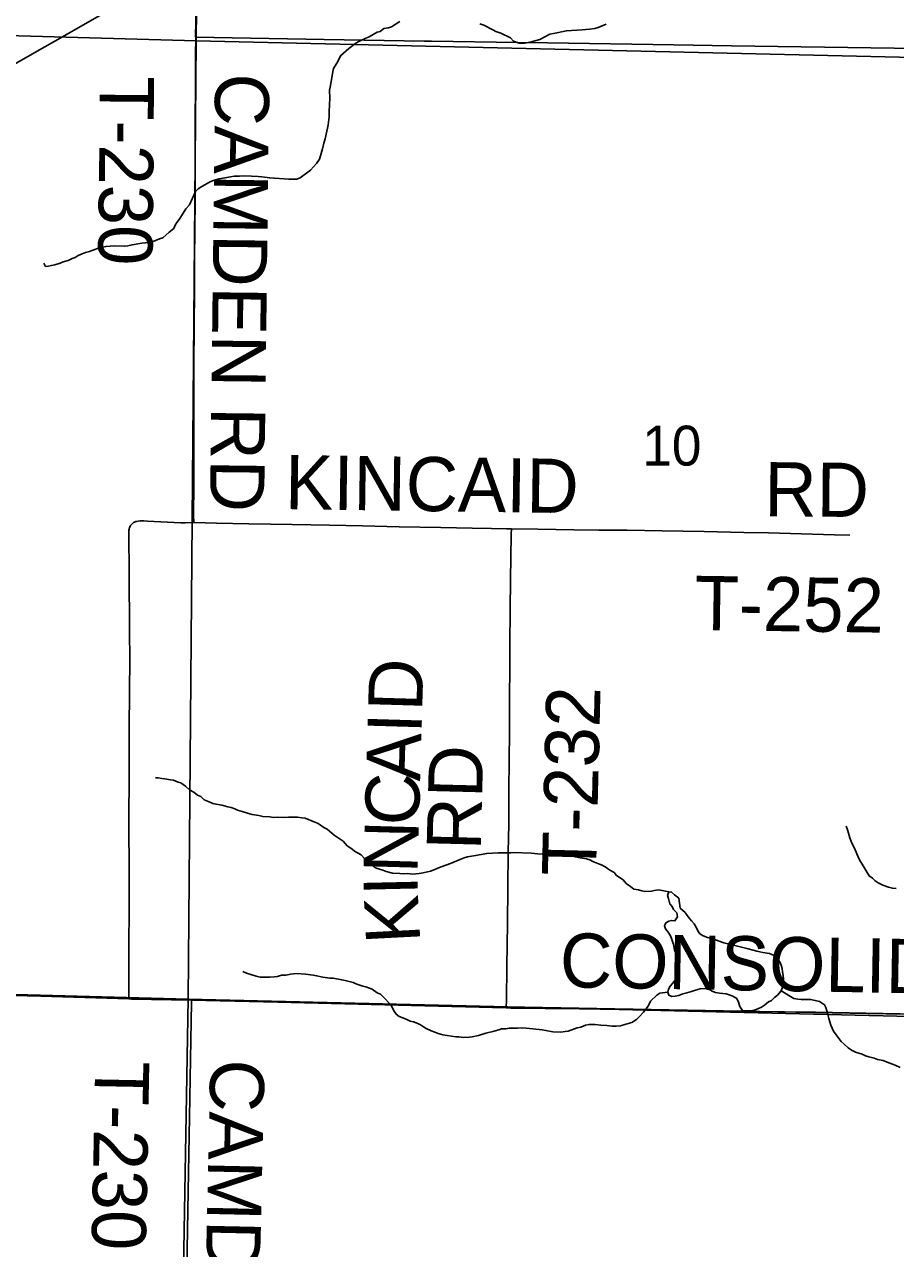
# Model space of a CAD drawing. Extents: x 0 to 34, y 0 to 22.
# Drawn here: x 25.481 to 25.938, y 17.215 to 17.857 of the extents above; entities that cross this region are included whole.
import ezdxf

# ---------------------------------------------------------------- set-up
doc = ezdxf.new("R2010")
doc.units = 0
for name, color, linetype in [('GM_X_Corporation', 7, 'Continuous'), ('GM_X_County_Road', 7, 'Continuous'), ('GM_X_County_Road_Text', 7, 'Continuous'), ('GM_X_Minor_River', 7, 'Continuous'), ('GM_X_Section', 7, 'Continuous'), ('GM_X_Section_Text', 7, 'Continuous'), ('GM_X_State_Route', 7, 'Continuous'), ('GM_X_Township', 7, 'Continuous'), ('GM_X_Township_Road', 7, 'Continuous'), ('GM_X_Township_Road_Text', 7, 'Continuous'), ('SC_Scratch1', 7, 'Continuous')]:
    doc.layers.add(name, color=color, linetype=linetype)

msp = doc.modelspace()

# ---------------------------------------------------------------- linework, layer by layer
at = {"layer": 'GM_X_Corporation'}
msp.add_lwpolyline([(26.05911, 17.84256), (25.85184, 17.84569), (25.82157, 17.84614), (25.75513, 17.84714), (25.73967, 17.84737), (25.69432, 17.84806), (25.69042, 17.84812), (25.63797, 17.84891), (25.57052, 17.85015), (25.57131, 17.89123)], dxfattribs=at)
at = {"layer": 'GM_X_County_Road'}
for points in [[(25.01331, 17.35912), (25.07885, 17.35735), (25.11483, 17.35638), (25.16488, 17.35487), (25.21328, 17.3539), (25.30505, 17.35181), (25.37943, 17.34967), (25.44651, 17.34801), (25.48937, 17.34696), (25.53551, 17.34557)], [(25.53551, 17.34557), (25.53688, 17.34553), (25.56843, 17.34486)], [(25.56843, 17.34486), (25.6136, 17.34389), (25.65584, 17.34285), (25.69091, 17.34191), (25.73359, 17.34085), (25.73594, 17.34079), (25.77197, 17.34038), (25.7937, 17.33996), (25.81638, 17.33963), (25.86328, 17.33902), (25.89585, 17.33857), (25.94025, 17.33778), (25.97348, 17.3371), (26.02504, 17.33614), (26.09925, 17.33463), (26.12596, 17.33417), (26.16259, 17.33362), (26.17764, 17.33314)]]:
    msp.add_lwpolyline(points, dxfattribs=at)
at = {"layer": 'GM_X_Minor_River'}
for points in [[(25.67769, 17.85832), (25.67341, 17.85562), (25.67168, 17.85511), (25.66938, 17.85462), (25.66743, 17.85316), (25.6659, 17.85284), (25.66163, 17.85033), (25.65989, 17.84963), (25.6566, 17.84803), (25.65466, 17.84696), (25.65095, 17.84424), (25.64664, 17.8404), (25.6452, 17.83741), (25.64298, 17.83369), (25.64254, 17.83219), (25.64227, 17.82992), (25.64111, 17.82388), (25.64087, 17.82237), (25.64091, 17.81819), (25.64066, 17.81117), (25.64056, 17.80832), (25.64004, 17.80416), (25.63979, 17.80246), (25.63935, 17.80076), (25.63845, 17.79681), (25.6378, 17.79455), (25.63712, 17.79153), (25.63646, 17.78908), (25.6356, 17.78608), (25.634, 17.78385), (25.63083, 17.78035), (25.62537, 17.77636), (25.62363, 17.77567), (25.61945, 17.77562)], [(25.78601, 17.85701), (25.78177, 17.85526), (25.78004, 17.85475), (25.77736, 17.85427), (25.77526, 17.85416), (25.77336, 17.85403), (25.76783, 17.85366), (25.76517, 17.85356), (25.75827, 17.85209), (25.75636, 17.85178), (25.75112, 17.84892), (25.7492, 17.84842), (25.74613, 17.84757), (25.74307, 17.84692), (25.74041, 17.84701), (25.7374, 17.84807), (25.73576, 17.84984), (25.73071, 17.85229), (25.72808, 17.85314), (25.72659, 17.85395), (25.72173, 17.8564), (25.71967, 17.85723)], [(25.61945, 17.77562), (25.61699, 17.7759), (25.61187, 17.77626), (25.6094, 17.77635), (25.60523, 17.77688), (25.60334, 17.77713), (25.59631, 17.77738), (25.59365, 17.77728), (25.59079, 17.77719), (25.58888, 17.77687), (25.58295, 17.77575), (25.57969, 17.77492), (25.57776, 17.77403), (25.57388, 17.77189), (25.57193, 17.77063), (25.57055, 17.76916), (25.56726, 17.76224), (25.56547, 17.76002), (25.56406, 17.75779), (25.56186, 17.75445), (25.56066, 17.75297), (25.55985, 17.75148), (25.55903, 17.7498), (25.55668, 17.74779), (25.55334, 17.74487), (25.55161, 17.74436), (25.54833, 17.74295), (25.54681, 17.74282), (25.54432, 17.74233), (25.5424, 17.74202), (25.53724, 17.74125), (25.53495, 17.74076), (25.53322, 17.74044), (25.52772, 17.74063), (25.52353, 17.7404), (25.52161, 17.7399), (25.5195, 17.7394), (25.51661, 17.73836), (25.51487, 17.73766), (25.51276, 17.73716), (25.51103, 17.73646), (25.50891, 17.73559), (25.50735, 17.7345), (25.50581, 17.73399), (25.50368, 17.73292), (25.50099, 17.73225), (25.49945, 17.73155), (25.49657, 17.7307), (25.49484, 17.73038), (25.49331, 17.73005), (25.49178, 17.72992), (25.4909, 17.73166)], [(25.55286, 17.46125), (25.55097, 17.46151), (25.54945, 17.46156)], [(25.81885, 17.40184), (25.81356, 17.40278), (25.81126, 17.40248), (25.80973, 17.40216), (25.8063, 17.4019), (25.80479, 17.40233), (25.80291, 17.40277), (25.80045, 17.40324), (25.79879, 17.40463), (25.79657, 17.40622), (25.79492, 17.40799), (25.79139, 17.41039), (25.79011, 17.41196), (25.78787, 17.41318), (25.78602, 17.41457), (25.78397, 17.41578), (25.78247, 17.41621), (25.77891, 17.41767), (25.77741, 17.41848), (25.77572, 17.41911), (25.77232, 17.41961), (25.76987, 17.42007), (25.76798, 17.42052), (25.764, 17.42085), (25.7604, 17.42116), (25.75888, 17.42122), (25.75509, 17.42154), (25.75319, 17.4216), (25.75015, 17.42171), (25.74655, 17.42202), (25.73743, 17.42234), (25.73591, 17.4222), (25.73306, 17.4223), (25.72925, 17.42225), (25.72335, 17.42188), (25.71742, 17.42076), (25.71321, 17.42015), (25.71148, 17.41964), (25.70878, 17.41859), (25.70434, 17.41665), (25.69934, 17.41493), (25.6976, 17.41423), (25.69606, 17.41352), (25.69374, 17.41265), (25.68991, 17.41165), (25.6878, 17.41134), (25.68437, 17.41108), (25.68191, 17.41136), (25.67981, 17.41124), (25.67773, 17.41131), (25.67394, 17.41163), (25.67054, 17.41251), (25.66885, 17.41314), (25.66528, 17.41421), (25.6625, 17.41621), (25.65918, 17.41918), (25.65735, 17.42114), (25.654, 17.42316), (25.65252, 17.42435), (25.6501, 17.42595), (25.6479, 17.42831), (25.64326, 17.43151), (25.63957, 17.43468), (25.63789, 17.4355), (25.63493, 17.43769), (25.63305, 17.43833), (25.62799, 17.4404), (25.62628, 17.44065), (25.62401, 17.44092), (25.62135, 17.44101), (25.61926, 17.44089), (25.6164, 17.4408), (25.61355, 17.4409), (25.61127, 17.44079), (25.60957, 17.44104), (25.60578, 17.44136), (25.6037, 17.44182), (25.6003, 17.44231), (25.59785, 17.44297), (25.59503, 17.44383), (25.59258, 17.44467), (25.59108, 17.4453), (25.58921, 17.44593), (25.58751, 17.44637), (25.58431, 17.44724), (25.58128, 17.44773), (25.57959, 17.44817), (25.57772, 17.44899), (25.57509, 17.45003), (25.57325, 17.45181), (25.57156, 17.45243), (25.56953, 17.45402), (25.56729, 17.45524), (25.56527, 17.45721), (25.56286, 17.45901), (25.56135, 17.45925), (25.55891, 17.46028), (25.5574, 17.46053), (25.55437, 17.46101), (25.55286, 17.46125)], [(25.93812, 17.40357), (25.93622, 17.40364), (25.93415, 17.40428), (25.93114, 17.40534), (25.92871, 17.40656), (25.92723, 17.40756), (25.92576, 17.40894), (25.92409, 17.41014), (25.92085, 17.41538), (25.91887, 17.41849), (25.91746, 17.42177), (25.91623, 17.42467), (25.915, 17.42737), (25.91395, 17.43006), (25.91309, 17.43256), (25.91258, 17.43429), (25.91189, 17.43622)], [(25.82405, 17.39843), (25.82183, 17.40022), (25.82036, 17.4016), (25.81885, 17.40184), (25.8182, 17.39977), (25.81872, 17.39823), (25.81938, 17.39555), (25.82066, 17.39399), (25.82137, 17.39244), (25.82302, 17.39067), (25.82351, 17.38857), (25.82211, 17.38653), (25.82041, 17.38677), (25.81887, 17.38645), (25.81732, 17.38555), (25.81669, 17.38386), (25.81721, 17.38233), (25.81848, 17.38057), (25.81974, 17.37863), (25.82043, 17.3767), (25.82112, 17.37459), (25.82162, 17.37248), (25.82194, 17.37095), (25.82371, 17.36709), (25.82422, 17.36555), (25.82433, 17.36327), (25.82444, 17.3608), (25.82381, 17.35911), (25.82297, 17.35705), (25.82215, 17.35537), (25.82076, 17.3537), (25.81957, 17.35223), (25.81876, 17.35073), (25.81832, 17.34904), (25.81883, 17.3475), (25.82052, 17.34687), (25.82224, 17.347), (25.82415, 17.34732), (25.82627, 17.34819), (25.82838, 17.34869), (25.83069, 17.34956), (25.83281, 17.35025), (25.8353, 17.35092), (25.83759, 17.35103), (25.84004, 17.35056), (25.84191, 17.34955), (25.84341, 17.34893), (25.84549, 17.34866), (25.8489, 17.34817), (25.85059, 17.34773), (25.85247, 17.34709), (25.85452, 17.34588), (25.8554, 17.34395), (25.85608, 17.34165), (25.85753, 17.33951), (25.85942, 17.33925), (25.8617, 17.33936), (25.86381, 17.33967), (25.86593, 17.34054), (25.86748, 17.34125), (25.86903, 17.34233), (25.87118, 17.34397), (25.87273, 17.34467), (25.87431, 17.34633), (25.87588, 17.34761), (25.87785, 17.34982), (25.87849, 17.35169), (25.87875, 17.35359), (25.87902, 17.35586), (25.8789, 17.35795), (25.87859, 17.35986), (25.87827, 17.36158), (25.87776, 17.36331), (25.87706, 17.36504), (25.87579, 17.3668), (25.87413, 17.36838), (25.8717, 17.36941), (25.86829, 17.36991), (25.8666, 17.37035), (25.86509, 17.37059), (25.86321, 17.37123), (25.86057, 17.3718)], [(25.86057, 17.3718), (25.85208, 17.37389), (25.85058, 17.37433), (25.84775, 17.37499), (25.84531, 17.37584), (25.84249, 17.37689), (25.84061, 17.37752), (25.8391, 17.37776), (25.83685, 17.3786), (25.83518, 17.3798), (25.8341, 17.38136), (25.83339, 17.3829), (25.83213, 17.38504), (25.83086, 17.3866), (25.82903, 17.38857), (25.8274, 17.3909), (25.82482, 17.39327), (25.82405, 17.39843)], [(25.81832, 17.34904), (25.81412, 17.34862), (25.81256, 17.34753), (25.80922, 17.34442), (25.80799, 17.3418), (25.80559, 17.33865), (25.80323, 17.33627), (25.80185, 17.33479), (25.79951, 17.33317), (25.79586, 17.33215), (25.79355, 17.33147), (25.79127, 17.33136), (25.78917, 17.33124), (25.78634, 17.33172), (25.78311, 17.33184), (25.78027, 17.33212), (25.77704, 17.33224), (25.77512, 17.33173), (25.77261, 17.33068), (25.7707, 17.33037), (25.76607, 17.32863), (25.76455, 17.32849), (25.76226, 17.32819), (25.75808, 17.32834), (25.7543, 17.32904), (25.75241, 17.32929), (25.74748, 17.32985), (25.74218, 17.33041), (25.73952, 17.33031), (25.73514, 17.33028), (25.73342, 17.32996), (25.73113, 17.32985), (25.72959, 17.32933), (25.72652, 17.32849), (25.72288, 17.32766), (25.71904, 17.32647), (25.71559, 17.32564), (25.71406, 17.3255), (25.7112, 17.32541), (25.70874, 17.32568), (25.70703, 17.32574), (25.70022, 17.32674), (25.69778, 17.3274), (25.69609, 17.32822), (25.69421, 17.32885), (25.6916, 17.33008), (25.6901, 17.33089), (25.68862, 17.3319), (25.68712, 17.33271), (25.68487, 17.33354), (25.68318, 17.33398), (25.68131, 17.33481), (25.67924, 17.33564), (25.67737, 17.33628), (25.6757, 17.33767), (25.67444, 17.33961), (25.67338, 17.34193), (25.67027, 17.34545), (25.66751, 17.34802), (25.66583, 17.34884), (25.66323, 17.35064), (25.66173, 17.35126), (25.65985, 17.3519), (25.65835, 17.35233), (25.65515, 17.35339), (25.65328, 17.35422), (25.64895, 17.35532), (25.64724, 17.35556), (25.64271, 17.35648), (25.641, 17.35654), (25.63722, 17.35705), (25.63401, 17.35774), (25.63231, 17.35798), (25.62814, 17.35851), (25.6234, 17.35886), (25.62035, 17.35859), (25.61805, 17.3581), (25.61558, 17.358), (25.61346, 17.35731), (25.61175, 17.35718), (25.60946, 17.35707), (25.60661, 17.35698), (25.60433, 17.35706), (25.60225, 17.35751), (25.59943, 17.35837), (25.59717, 17.35902), (25.59531, 17.36003)], [(25.90131, 17.34102), (25.9006, 17.34256), (25.898, 17.34418), (25.89574, 17.34482), (25.89329, 17.34529), (25.89158, 17.34535), (25.88834, 17.34527), (25.88664, 17.34552), (25.88456, 17.34578), (25.87785, 17.34982)], [(25.94032, 17.30964), (25.9377, 17.31087), (25.93338, 17.31235), (25.93132, 17.31319), (25.9283, 17.31386), (25.92661, 17.31449), (25.92379, 17.31516), (25.9221, 17.31579), (25.92041, 17.31661), (25.91684, 17.31768), (25.91478, 17.3187), (25.91292, 17.31991), (25.9109, 17.32188), (25.90924, 17.32326), (25.9067, 17.32677), (25.90525, 17.32872), (25.90384, 17.33181), (25.90282, 17.33527), (25.90232, 17.33738), (25.90182, 17.33929), (25.90131, 17.34102)]]:
    msp.add_lwpolyline(points, dxfattribs=at)
at = {"layer": 'GM_X_Section'}
for points in [[(25.08458, 18.38093), (25.5617, 18.37181), (25.57628, 18.37165), (25.57077, 17.84822), (25.07407, 17.86217)], [(25.57628, 18.37165), (26.06944, 18.36744), (26.0861, 18.36703), (26.07549, 17.83653), (25.57077, 17.84822)], [(25.57077, 17.84822), (25.56671, 17.3454), (25.06186, 17.35916), (25.07407, 17.86217)], [(25.57077, 17.84822), (26.07549, 17.83653), (26.0699, 17.33338), (25.56671, 17.3454)], [(25.06186, 17.35916), (25.56671, 17.3454), (25.55809, 16.8497), (25.05294, 16.85911)], [(25.56671, 17.3454), (26.0699, 17.33338), (26.0572, 16.84119), (25.55809, 16.8497)]]:
    msp.add_lwpolyline(points, close=True, dxfattribs=at)
at = {"layer": 'GM_X_State_Route'}
msp.add_lwpolyline([(25.11016, 17.62284), (25.11217, 17.62436), (25.11687, 17.62793), (25.13052, 17.63822), (25.13648, 17.64238), (25.13905, 17.6441), (25.14422, 17.64741), (25.15652, 17.65472), (25.19902, 17.67927), (25.23276, 17.69851), (25.25619, 17.71199), (25.28763, 17.7296), (25.31286, 17.74367), (25.39575, 17.79085), (25.42766, 17.8088), (25.431, 17.81069), (25.44905, 17.82093), (25.46468, 17.82988), (25.48739, 17.84275), (25.50061, 17.85033), (25.55054, 17.87902), (25.56703, 17.88848)], dxfattribs=at)
at = {"layer": 'GM_X_Township'}
msp.add_lwpolyline([(24.86059, 17.36313), (25.53318, 17.34594), (25.56701, 17.34529), (25.6976, 17.34237), (25.72151, 17.34163), (25.73372, 17.34145), (26.18926, 17.3331), (26.20844, 17.33277), (26.32558, 17.33128)], dxfattribs=at)
at = {"layer": 'GM_X_Township_Road'}
for points in [[(25.57058, 17.84964), (25.57087, 17.86554), (25.57091, 17.87575), (25.57097, 17.88374), (25.57104, 17.88541), (25.57111, 17.88729), (25.57136, 17.89097)], [(25.56954, 17.59666), (25.5695, 17.59825), (25.56956, 17.61608), (25.56964, 17.65987), (25.5696, 17.67416), (25.56982, 17.70212), (25.56994, 17.7136), (25.57002, 17.73131), (25.5702, 17.7515), (25.57024, 17.76206), (25.57035, 17.77448), (25.57034, 17.78412), (25.5703, 17.79281), (25.57036, 17.80741), (25.57041, 17.82325), (25.57049, 17.84127), (25.57058, 17.84964)], [(25.53551, 17.34557), (25.53551, 17.34739), (25.53557, 17.36654), (25.53572, 17.39948), (25.53567, 17.41564), (25.53557, 17.43429), (25.53557, 17.44392), (25.53561, 17.45851), (25.53563, 17.47032), (25.5357, 17.48648), (25.53586, 17.50792), (25.53601, 17.52253), (25.53591, 17.53931), (25.53567, 17.56821), (25.53547, 17.59028), (25.53556, 17.59144), (25.53567, 17.59206), (25.5359, 17.59283), (25.53614, 17.5934), (25.53641, 17.59389), (25.53676, 17.59439), (25.53724, 17.5949), (25.5376, 17.59521), (25.53796, 17.59547), (25.53839, 17.5957), (25.5389, 17.5959), (25.53923, 17.59599), (25.53965, 17.59609), (25.54043, 17.59623), (25.54136, 17.59633), (25.54332, 17.59634), (25.54534, 17.59628), (25.56285, 17.59534), (25.56415, 17.59534), (25.56525, 17.59539), (25.56957, 17.5956), (25.56954, 17.59666)], [(25.56957, 17.5956), (25.58143, 17.59517), (25.59852, 17.59488), (25.62119, 17.59442), (25.64076, 17.59411), (25.65815, 17.59375), (25.67741, 17.59331), (25.69915, 17.59288), (25.71561, 17.59257), (25.72586, 17.59239), (25.73363, 17.59228), (25.73623, 17.59225), (25.75009, 17.59209), (25.76903, 17.59175), (25.78208, 17.59157), (25.79699, 17.59144), (25.81531, 17.59119), (25.83737, 17.59079), (25.85818, 17.59037), (25.87122, 17.59014), (25.90577, 17.58904), (25.91391, 17.58884)], [(25.73359, 17.34085), (25.73365, 17.34516), (25.73387, 17.36255), (25.73416, 17.38522), (25.73443, 17.40385), (25.73458, 17.42276), (25.73486, 17.43704), (25.73489, 17.45689), (25.73505, 17.46869), (25.7352, 17.48764), (25.73533, 17.49944), (25.73535, 17.52335), (25.73544, 17.53174), (25.73566, 17.54913), (25.73584, 17.56621), (25.73597, 17.57677), (25.73619, 17.5895), (25.73623, 17.59225)], [(25.56843, 17.34486), (25.53688, 17.34553), (25.53551, 17.34557)], [(25.56208, 17.00998), (25.5624, 17.02583), (25.563, 17.04902), (25.56345, 17.07013), (25.56371, 17.08223), (25.56437, 17.12293), (25.56505, 17.16144), (25.56551, 17.18412), (25.56587, 17.204), (25.56663, 17.24469), (25.56736, 17.28352), (25.56791, 17.31396), (25.56841, 17.34378), (25.56843, 17.34486)]]:
    msp.add_lwpolyline(points, dxfattribs=at)
at = {"layer": 'SC_Scratch1'}
msp.add_lwpolyline([(24.86059, 17.36313), (25.53318, 17.34594), (25.56701, 17.34529), (25.6976, 17.34237), (25.72151, 17.34163), (25.73372, 17.34145), (26.18926, 17.3331), (26.20844, 17.33277), (26.32558, 17.33128)], dxfattribs=at)

# ---------------------------------------------------------------- texts
at = {"layer": 'GM_X_County_Road_Text'}
msp.add_text('CONSOLIDATED', height=0.0284091, rotation=359.01978, dxfattribs=at).set_placement((25.76152, 17.35175))
at = {"layer": 'GM_X_Section_Text'}
msp.add_text('10', height=0.020928, rotation=0.00001, dxfattribs=at).set_placement((25.80487, 17.62539))
at = {"layer": 'GM_X_Township_Road_Text'}
for s, height, rotation, p in [('T-230', 0.028409, 269.43832, (25.52036, 17.82981)), ('CAMDEN RD', 0.028409, 269.30977, (25.58084, 17.83127)), ('KINCAID', 0.028409, 359.18612, (25.61732, 17.60258)), ('RD', 0.028409, 359.50635, (25.86893, 17.59883)), ('T-252', 0.028409, 359.15794, (25.83227, 17.53919)), ('D', 0.02841, 88.32773, (25.68941, 17.49628)), ('T-232', 0.028409, 88.59766, (25.78063, 17.40986)), ('I', 0.02841, 88.32735, (25.68907, 17.48462)), ('A', 0.02841, 88.32773, (25.68834, 17.45963)), ('RD', 0.028409, 88.51889, (25.72015, 17.42342)), ('C', 0.02841, 88.32833, (25.68766, 17.43631)), ('N', 0.02841, 88.37688, (25.68695, 17.41132)), ('I', 0.02841, 91.29398, (25.68722, 17.40004)), ('K', 0.02841, 92.92736, (25.68848, 17.37529)), ('T-230', 0.028409, 268.87652, (25.51787, 17.31321)), ('CAMDEN', 0.028409, 268.73043, (25.57834, 17.31408))]:
    msp.add_text(s, height=height, rotation=rotation, dxfattribs=at).set_placement(p)

doc.saveas('drawing.dxf')
